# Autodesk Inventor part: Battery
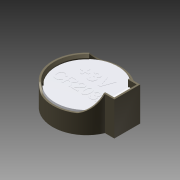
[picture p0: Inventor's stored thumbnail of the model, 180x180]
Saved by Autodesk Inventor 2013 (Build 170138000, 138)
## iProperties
Company: Autodesk Inc.
Created: 2005-12
Part Number: Battery
Document SubType Name: Modeling
Designer: Autodesk Inc.
Density: 1 g/cm^3
Mass: 1.86782 g
Surface Area: 20.1624 cm^2
Volume: 1.86782 cm^3
Material: Allgemein
Title: Personal Computer
Author: Autodesk Inc.
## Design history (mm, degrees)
sketch "Sketch1"
  geometry: L1 (0, 14)-(0, -14) reference; L2 (-14, 0)-(14, 0) reference; C1 r 10 at (0, 0)
  constraints: 2 midpoint, 1 centre point
  dimensions: "d0" = 20 diameter of C1
extrude "Extrusion1" new body sketch "Sketch1" distance "d1" = 10; taper "d2" = 0 deg
shell "Shell1" dims "d3" = 0.5
workplane "Work Plane1"
sketch "Sketch2"
  geometry: L1 (0, -2.995)-(0, 17.97) reference; L2 (-10, 10)-(10, 10) reference; L3 (-5.897, 5.5)-(4.679, 5.5); L4 (-10, 0)-(10, 0) reference; L5 (-11.792, 10)-(9.358, 10); A1 r 9.817 centre (-3.329, 14.975) between (-11.792, 10) and (-5.897, 5.5); A2 r 7.577 centre (2.273, 12.685) between (4.679, 5.5) and (9.358, 10)
  constraints: 4 end point, 4 point on circle, 2 centre point, 2 point on line, 1 collinear, 1 parallel
  dimensions: "d5" = 5.5 distance between parallel lines of L4 L3
emboss "Emboss1" sketch "Sketch2" dims "d6" = 0.5, "d7" = 0
fillet "Fillet1" dims "d8" = 2
mirror "Mirror1"
sketch "Sketch3"
  geometry: L1 (-13.591, 11.95)-(-5.956, 11.95); L2 (-5.956, 11.95)-(-5.956, -17.736); L3 (-5.956, -17.736)-(-13.591, -17.736); L4 (-13.591, -17.736)-(-13.591, 11.95)
  constraints: 8 end point, 2 parallel, 1 horizontal, 1 perpendicular
extrude "Extrusion2" cut sketch "Sketch3" distance "d9" = 3; taper "d10" = 0 deg
sketch "Sketch4"
  geometry: L1 (9.243, 3.817)-(12, 3.817); L2 (12, 3.817)-(12, -3.817); L3 (12, -3.817)-(9.243, -3.817); L4 (9.243, -3.817)-(9.243, 3.817); A1 r 10 centre (0, 0) between (9.243, -3.817) and (9.243, 3.817) reference
  constraints: 8 end point, 2 parallel, 1 horizontal, 1 perpendicular
  dimensions: "d11" = 12 distance from line of A1.centre L2
extrude "Extrusion3" join sketch "Sketch4" stored distance "d12" = 3; taper "d13" = 0 deg
sketch "Sketch5"
  geometry: L1 (9.243, -3.817)-(12, -3.817) reference; L2 (12, -3.817)-(12, 3.817) reference; L3 (12, 3.817)-(9.243, 3.817) reference; L4 (7.616, 3.317)-(11.5, 3.317); L5 (11.5, 3.317)-(11.5, -3.317); L6 (11.5, -3.317)-(7.616, -3.317); L7 (7.616, -3.317)-(7.616, 3.317)
  constraints: 8 end point, 2 parallel, 1 horizontal, 1 perpendicular
  dimensions: "d14" = 0.5 distance between parallel lines of L2 L5; "d15" = 0.5 distance between parallel lines of L3 L4; "d16" = 0.5 distance between parallel lines of L1 L6
extrude "Extrusion4" cut sketch "Sketch5" stored distance "d17" = 3; taper "d18" = 0 deg
sweep "Sweep1" dims "d22" = 0
sketch "Sketch8"
  geometry: C1 r 9.25 at (-8.902, 3.317); A1 r 9.5 centre (-8.902, 3.317) between (0, 6.633) and (0, 0) reference
  constraints: 1 centre point, 1 coincident
  dimensions: "d23" = 18.5 diameter of C1
extrude "Extrusion5" join sketch "Sketch8" distance "d24" = 5.4; taper "d25" = 0 deg
sketch "Sketch9"
  geometry: L1 (-23.302, 3.317)-(7.498, 3.317) reference; L2 (0.598, 6.317)-(1.098, 6.317); L3 (1.098, 6.317)-(1.098, 0.317); L4 (1.098, 0.317)-(0.598, 0.317); L5 (0.598, 0.317)-(0.598, 6.317); L6 (-8.902, 22.589)-(-8.902, -15.955) reference
  constraints: 8 end point, 2 parallel, 1 horizontal, 1 perpendicular, 1 other
  dimensions: "d26" = 9.5 distance between parallel lines of L5 L6; "d27" = 0.5 distance of L3.end L4.end; "d28" = 6 distance of L2.end L3.end
extrude "Extrusion6" join sketch "Sketch9" distance "d29" = 8; taper "d30" = 0 deg
sketch "Sketch10"
  geometry: L1 (-9.5, 0.5)-(-9.5, 8.5) reference; L2 (-9.5, 8.5)-(-8, 6); L3 (-8, 6)-(-9.5, 6); L4 (-9.25, 5.9)-(9.25, 5.9) reference; L5 (-10, 0.5)-(-10, 8.5) reference
  constraints: 4 end point, 1 perpendicular, 1 point on line
  dimensions: "d31" = 0.1 distance between parallel lines of L3 L4; "d32" = 2 distance from line of L5 L2.end
extrude "Extrusion7" join sketch "Sketch10" stored distance "d33" = 6; taper "d34" = 0 deg
sketch "Sketch11"
  geometry: L1 (-14.4, 0)-(16.4, 0) reference; L2 (9.5, 3)-(8, 3) reference; L3 (8, -3)-(9.5, -3) reference; L4 (9.5, 3)-(8, 3) reference; L5 (8, -3)-(8, 3) reference; L6 (8, -3)-(9.5, -3) reference; L7 (9.5, -3)-(9.5, 3) reference; L8 (8, 2.5)-(9.5, 2.5); L9 (9.5, 2.5)-(9.5, -2.5); L10 (9.5, -2.5)-(8, -2.5); L11 (8, -2.5)-(8, 2.5)
  constraints: 8 end point, 2 parallel, 2 point on line, 1 horizontal, 1 perpendicular
  dimensions: "d35" = 0.5 distance between parallel lines of L2 L8; "d36" = 0.5 distance between parallel lines of L3 L10 (= d35)
extrude "Extrusion8" cut sketch "Sketch11" stored distance "d37" = 6; taper "d38" = 0 deg
sketch "Sketch12"
  geometry: L1 (-5.019, 4.976)-(3.817, 4.976); L2 (3.817, 4.976)-(3.817, 1.404); L3 (3.817, 1.404)-(-5.019, 1.404); L4 (-5.019, 1.404)-(-5.019, 4.976); L5 (-7.721, 0)-(10.217, 0); L6 (10.217, 0)-(10.217, -3.62); L7 (10.217, -3.62)-(-7.721, -3.62); L8 (-7.721, -3.62)-(-7.721, 0)
  constraints: 4 other
extrude "Extrusion9" join sketch "Sketch12" distance "d39" = 0.05; taper "d40" = 0 deg
body "Solid1"
sketch "Sketch6"
  geometry: L1 (9.5, 0.5)-(9.5, 7) reference; L2 (9.5, 7)-(9, 6.3); L3 (9, 6.3)-(9, 6); L4 (9, 6)-(9.5, 6); L5 (9.5, 6)-(9.5, 7)
  constraints: 8 end point, 1 collinear, 1 parallel, 1 perpendicular, 1 point on line
  dimensions: "d19" = 1 distance of L4.end L1.end; "d20" = 0.3 distance of L2.end L3.end; "d21" = 0.5 distance between parallel lines of L1 L3
sketch "Sketch7"
  geometry: A1 r 9.5 centre (0, 0) between (-6.323, 7.09) and (-6.323, -7.09) reference
node "Projected Loop1"
other parameters: "d4" = 15
